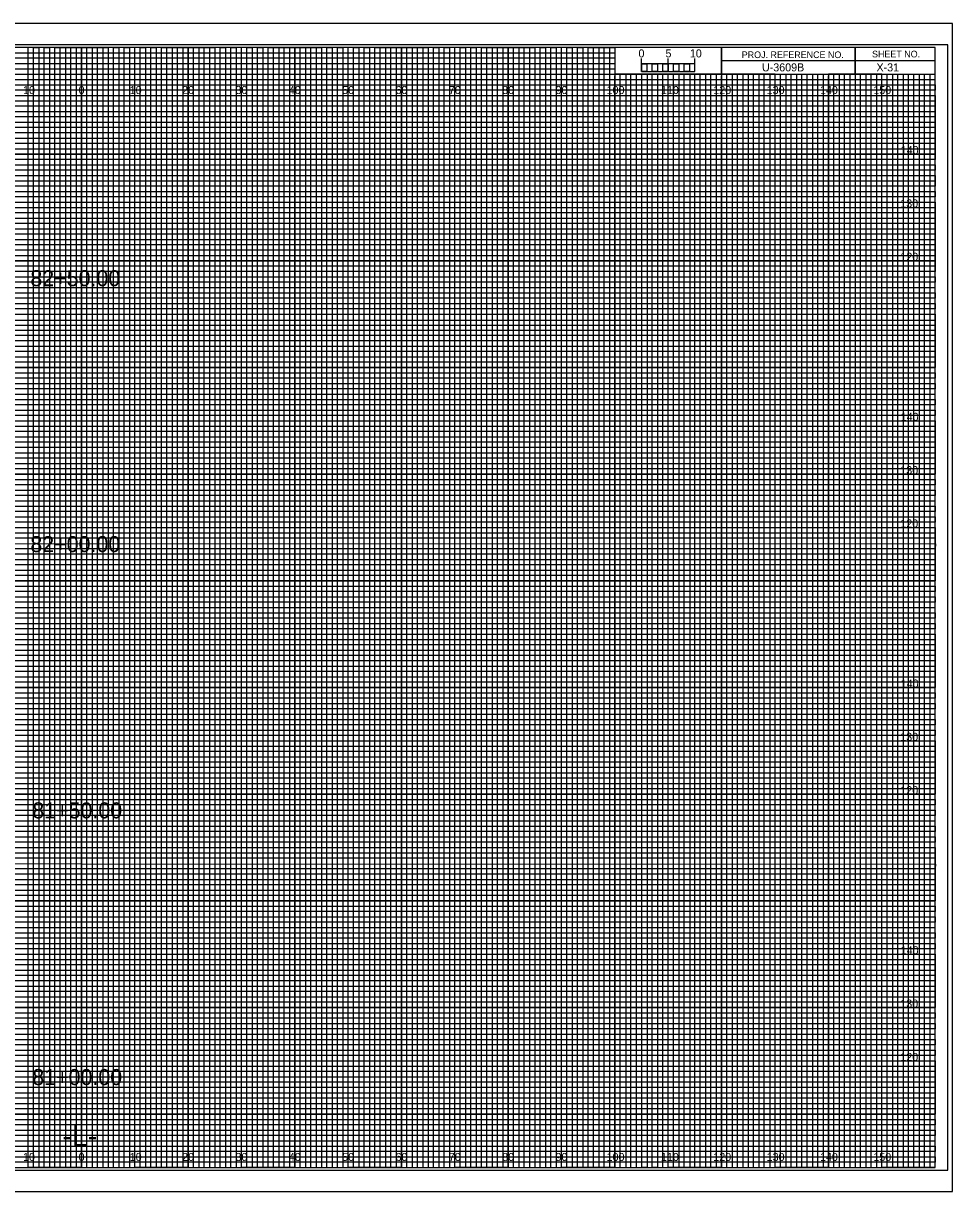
# Model space of a CAD drawing. Extents: x -13 to 329, y -17 to 10994.
# Drawn here: x 149.1 to 323.3, y 6375.5 to 6594.5 of the extents above; entities that cross this region are included whole.
import ezdxf

# ---------------------------------------------------------------- set-up
doc = ezdxf.new("R2010")
doc.units = 0
for name, color, linetype in [('Prop XS Alignment Label', 7, 'Continuous'), ('Prop XS Bar Scale Labels', 7, 'Continuous'), ('Prop XS Elevation Labels', 7, 'Continuous'), ('Prop XS Offset Labels', 7, 'Continuous'), ('Prop XS Project Number', 7, 'Continuous'), ('Prop XS Sheet Number', 7, 'Continuous'), ('Prop XS Station Labels', 7, 'Continuous'), ('Sheet Cross Section CELL', 7, 'Continuous'), ('Sheet Cross Section Grid Major CELL', 7, 'Continuous'), ('Sheet Cross Section Grid Middle CELL', 7, 'Continuous'), ('Sheet Cross Section Grid Minor 1 CELL', 7, 'Continuous'), ('Sheet Cross Section Grid Minor 2 CELL', 7, 'Continuous'), ('Sheet Cross Section Scale CELL', 7, 'Continuous'), ('Sheet Cutting Line CELL', 7, 'Continuous'), ('Sheet DOT Grid CELL', 7, 'Continuous'), ('Sheet Plot Border Inside CELL', 7, 'Continuous'), ('Sheet Plot Border Outside CELL', 7, 'Continuous')]:
    doc.layers.add(name, color=color, linetype=linetype)

msp = doc.modelspace()

# ---------------------------------------------------------------- linework, layer by layer
at = {"layer": 'Sheet Cross Section CELL'}
for p, q in [((305, 6590), (305, 6585)), ((305, 6585), (305, 6590)), ((280, 6587.5), (280, 6585)), ((320, 6587.49), (280, 6587.49)), ((280, 6585), (320, 6585))]:
    msp.add_line(p, q, dxfattribs=at)
for points in [[(320, 6590), (0, 6590), (0, 6380), (320, 6380)], [(280, 6590), (260, 6590), (260, 6585.03), (280, 6585.03)], [(320, 6590), (280, 6590), (280, 6585), (320, 6585)]]:
    msp.add_lwpolyline(points, close=True, dxfattribs=at)
at = {"layer": 'Sheet Cross Section Grid Major CELL'}
for p, q in [((150, 6590), (140, 6590)), ((150, 6380), (150, 6590)), ((170, 6590), (160, 6590)), ((160, 6590), (160, 6380)), ((170, 6380), (170, 6590)), ((190, 6590), (180, 6590)), ((180, 6590), (180, 6380)), ((190, 6380), (190, 6590)), ((210, 6590), (200, 6590)), ((200, 6590), (200, 6380)), ((210, 6380), (210, 6590)), ((230, 6590), (220, 6590)), ((220, 6590), (220, 6380)), ((230, 6380), (230, 6590)), ((250, 6590), (240, 6590)), ((240, 6590), (240, 6380)), ((250, 6380), (250, 6590)), ((260, 6590), (260, 6380)), ((270, 6380), (270, 6585)), ((290, 6585), (280, 6585)), ((280, 6585), (280, 6380)), ((290, 6380), (290, 6585)), ((310, 6585), (300, 6585)), ((300, 6585), (300, 6380)), ((310, 6380), (310, 6585)), ((160, 6380), (150, 6380)), ((180, 6380), (170, 6380)), ((200, 6380), (190, 6380)), ((220, 6380), (210, 6380)), ((240, 6380), (230, 6380)), ((260, 6380), (250, 6380)), ((280, 6380), (270, 6380)), ((300, 6380), (290, 6380)), ((320, 6380), (310, 6380)), ((320, 6380), (320, 6380))]:
    msp.add_line(p, q, dxfattribs=at)
for points in [[(0, 6580), (320, 6580), (320, 6570), (0, 6570)], [(0, 6560), (320, 6560), (320, 6550), (0, 6550)], [(0, 6540), (320, 6540), (320, 6530), (0, 6530)], [(0, 6520), (320, 6520), (320, 6510), (0, 6510)], [(0, 6500), (320, 6500), (320, 6490), (0, 6490)], [(0, 6480), (320, 6480), (320, 6470), (0, 6470)], [(0, 6460), (320, 6460), (320, 6450), (0, 6450)], [(0, 6440), (320, 6440), (320, 6430), (0, 6430)], [(0, 6420), (320, 6420), (320, 6410), (0, 6410)], [(0, 6400), (320, 6400), (320, 6390), (0, 6390)]]:
    msp.add_lwpolyline(points, dxfattribs=at)
at = {"layer": 'Sheet Cross Section Grid Middle CELL'}
for points in [[(145, 6380), (155, 6380), (155, 6590), (165, 6590), (165, 6380), (175, 6380), (175, 6590), (185, 6590), (185, 6380), (195, 6380), (195, 6590), (205, 6590), (205, 6380), (215, 6380), (215, 6590), (225, 6590), (225, 6380), (235, 6380), (235, 6590), (245, 6590), (245, 6380), (255, 6380), (255, 6590), (259.93, 6590), (260, 6590), (260, 6585), (264.99, 6585), (264.99, 6380), (275, 6380), (275, 6585), (285, 6585), (285, 6380), (295, 6380), (295, 6585), (305, 6585), (305, 6380), (315, 6380), (315, 6585)], [(0, 6585), (275, 6585)], [(0, 6565), (320, 6565), (320, 6575), (0, 6575)], [(0, 6545), (320, 6545), (320, 6555), (0, 6555)], [(0, 6525), (320, 6525), (320, 6535), (0, 6535)], [(0, 6505), (320, 6505), (320, 6515), (0, 6515)], [(0, 6485), (320, 6485), (320, 6495), (0, 6495)], [(0, 6465), (320, 6465), (320, 6475), (0, 6475)], [(0, 6445), (320, 6445), (320, 6455), (0, 6455)], [(0, 6425), (320, 6425), (320, 6435), (0, 6435)], [(0, 6405), (320, 6405), (320, 6415), (0, 6415)], [(0, 6385), (320, 6385), (320, 6395), (0, 6395)]]:
    msp.add_lwpolyline(points, dxfattribs=at)
at = {"layer": 'Sheet Cross Section Grid Minor 1 CELL'}
for p, q in [((0, 6589), (260, 6589)), ((260, 6587.98), (0, 6587.98)), ((260, 6589), (260, 6587.98)), ((0, 6587), (260, 6587)), ((260, 6585.89), (0, 6585.89)), ((260, 6587), (260, 6585.89)), ((0, 6584), (320, 6584))]:
    msp.add_line(p, q, dxfattribs=at)
for points in [[(0, 6583), (270, 6583), (320, 6583), (320, 6582), (0, 6582)], [(0, 6581), (320, 6581), (320, 6579), (0, 6579)], [(0, 6578), (320, 6578), (320, 6577), (0, 6576.98)], [(0, 6576), (320, 6576), (320, 6574), (0, 6574)], [(0, 6573), (320, 6573), (320, 6572), (0, 6572)], [(0, 6571), (320, 6571), (320, 6569), (0, 6569)], [(0, 6568), (320, 6568), (320, 6567), (0, 6567)], [(0, 6566), (320, 6566), (320, 6564), (0, 6564)], [(0, 6563), (320, 6563), (320, 6562), (0, 6562)], [(0, 6561), (320, 6561), (320, 6559), (0, 6559)], [(0, 6558), (320, 6558), (320, 6557), (0, 6557)], [(0, 6556), (320, 6556), (320, 6553.95), (320, 6553), (320, 6552), (0, 6552)], [(0, 6554), (320, 6554), (320, 6553), (0, 6553)], [(0, 6551), (320, 6551), (320, 6549), (0, 6549.03)], [(0, 6549.03), (320, 6549), (320, 6548), (0, 6548)], [(0, 6547), (320, 6547), (320, 6546), (0, 6546)], [(0, 6544), (320, 6544), (320, 6543), (0, 6543)], [(0, 6542), (320, 6542), (320, 6541), (0, 6541)], [(-0.07, 6538.89), (320, 6538.89), (320, 6537.88), (-0.07, 6537.88)], [(0, 6537), (320, 6537), (320, 6536), (0, 6536)], [(0, 6534), (320, 6534), (320, 6533), (0, 6533)], [(0, 6532), (320, 6532), (320, 6531), (0, 6531)], [(0, 6529), (320, 6529), (320, 6528), (0, 6528)], [(0, 6527), (320, 6527), (320, 6526), (0, 6526)], [(0, 6524), (320, 6524), (320, 6523), (0, 6523)], [(0, 6522), (320, 6522), (320, 6521), (0, 6521)], [(0, 6519), (320, 6519), (319.99, 6517.98), (0, 6518)], [(0, 6517), (320, 6517), (320, 6516), (0, 6516)], [(0, 6514), (320, 6514), (320, 6513), (0, 6513)], [(0, 6512), (320, 6512), (320, 6511), (0, 6511)], [(0, 6509), (320, 6509), (320, 6508), (0, 6508)], [(0, 6507), (320, 6507), (320, 6506), (0, 6506)], [(0, 6504), (320, 6504), (320, 6503), (0, 6503)], [(0, 6502), (320, 6502), (320, 6501), (0, 6501)], [(0, 6499), (320, 6499), (320, 6498), (0, 6498)], [(0, 6496.99), (320.07, 6496.91), (320, 6496), (0, 6496)], [(0, 6494), (320, 6494), (320, 6493), (0, 6493)], [(0, 6492), (320, 6492), (320, 6491), (0, 6491)], [(0, 6489), (320, 6489), (320, 6488), (0, 6488)], [(0, 6487), (320, 6487), (320, 6486), (0, 6486)], [(0, 6484), (320, 6484), (320, 6483), (0, 6483)], [(0, 6482), (320, 6482), (320, 6481), (0, 6481)], [(0, 6479), (320, 6479), (320, 6478), (0, 6478)], [(0, 6477), (320, 6477), (320, 6476), (0, 6476)], [(0, 6474), (320, 6474), (320, 6473), (0, 6473)], [(0, 6472), (320, 6472), (320, 6471), (0, 6471)], [(0, 6469), (320, 6469), (320, 6468), (0, 6468)], [(0, 6467), (320, 6467), (320, 6466), (0, 6466)], [(0, 6464), (320, 6464), (320, 6463), (0, 6463)], [(0, 6462), (320, 6462), (320, 6461), (0, 6461)], [(0, 6459), (320, 6459), (319.99, 6457.98), (0, 6458)], [(0, 6457), (320, 6457), (320, 6456), (0, 6456)], [(0, 6454), (320, 6454), (320, 6453), (0, 6453)], [(0, 6452), (320, 6452), (320, 6451), (0, 6451)], [(0, 6449), (320, 6449), (320, 6448), (0, 6448)], [(0, 6447), (320, 6447), (320, 6446), (0, 6446)], [(0, 6444), (320, 6444), (320, 6443), (0, 6443)], [(0, 6442), (320, 6442), (320, 6441), (0, 6441)], [(0, 6439), (320, 6439), (320, 6438), (0, 6438)], [(0, 6436.99), (320.07, 6436.91), (320, 6436), (0, 6436)], [(0, 6434), (320, 6434), (320, 6433), (0, 6433)], [(0, 6432), (320, 6432), (320, 6431), (0, 6431)], [(0, 6429), (320, 6429), (320, 6428), (0, 6428)], [(0, 6427), (320, 6427), (320, 6426), (0, 6426)], [(0, 6424), (320, 6424), (320, 6423), (0, 6423)], [(0, 6422), (320, 6422), (320, 6421), (0, 6421)], [(0, 6419), (320, 6419), (320, 6418), (0, 6418)], [(0, 6417), (320, 6417), (320, 6416), (0, 6416)], [(0, 6414), (320, 6414), (320, 6413), (0, 6413)], [(0, 6412), (320, 6412), (320, 6411), (0, 6411)], [(0, 6409), (320, 6409), (320, 6408), (0, 6408)], [(0, 6407), (320, 6407), (320, 6406), (0, 6406)], [(0, 6404), (320, 6404), (320, 6403), (0, 6403)], [(0, 6402), (320, 6402), (320, 6401), (0, 6401)], [(0, 6399), (320, 6399), (320, 6398), (0, 6398)], [(0, 6397), (320, 6397), (320, 6396), (0, 6396)], [(0, 6394), (320, 6394), (320, 6393), (0, 6393)], [(0, 6392), (320, 6392), (320, 6391), (0, 6391)], [(0, 6389), (320, 6389), (320, 6388), (0, 6388)], [(0, 6387), (320, 6387), (320, 6386), (0, 6386)], [(0, 6384), (320, 6384), (320, 6383), (0, 6383)], [(0, 6382), (320, 6382), (320, 6381), (0, 6381)]]:
    msp.add_lwpolyline(points, dxfattribs=at)
at = {"layer": 'Sheet Cross Section Grid Minor 2 CELL'}
for p, q in [((267, 6585), (266.01, 6585)), ((266.01, 6585), (266.01, 6380)), ((267, 6380), (267, 6585)), ((269, 6585), (268, 6585)), ((268, 6585), (268, 6380)), ((269, 6380), (269, 6585)), ((266.01, 6380), (265, 6380)), ((268, 6380), (267, 6380))]:
    msp.add_line(p, q, dxfattribs=at)
for points in [[(150, 6380), (151, 6380), (151, 6590), (152, 6590), (152, 6380)], [(152, 6380), (153, 6380), (153, 6590), (154, 6590), (154, 6380)], [(155, 6380), (156, 6380), (156, 6590), (157, 6590), (157, 6380)], [(157, 6380), (158, 6380), (158, 6590), (159, 6590), (159, 6380)], [(160, 6380), (161, 6380), (161, 6590), (162, 6590), (162, 6380)], [(162, 6380), (163, 6380), (163, 6590), (164, 6590), (164, 6380)], [(165, 6380), (166, 6380), (166, 6590), (167, 6590), (167, 6380)], [(167, 6380), (168, 6380), (168, 6590), (169, 6590), (169, 6380)], [(170, 6380), (171, 6380), (171, 6590), (172, 6590), (172, 6380)], [(172, 6380), (173, 6380), (173, 6590), (174, 6590), (174, 6380)], [(175, 6380), (176, 6380), (176, 6590), (177, 6590), (177, 6380)], [(177, 6380), (178, 6380), (178, 6590), (179, 6590), (179, 6380)], [(180, 6380), (181, 6380), (181, 6590), (182, 6590), (182, 6380)], [(182, 6380), (183, 6380), (183, 6590), (184, 6590), (184, 6380)], [(185, 6380), (186, 6380), (186, 6590), (187, 6590), (187, 6380)], [(187, 6380), (188, 6380), (188, 6590), (189, 6590), (189, 6380)], [(190, 6380), (191, 6380), (191, 6590), (192, 6590), (192, 6380)], [(192, 6380), (193, 6380), (193, 6590), (194, 6590), (194, 6380)], [(195, 6380), (196, 6380), (196, 6590), (197, 6590), (197, 6380)], [(197, 6380), (198, 6380), (198, 6590), (199, 6590), (199, 6380)], [(200, 6380), (201, 6380), (201, 6590), (202, 6590), (202, 6380)], [(202, 6380), (203, 6380), (203, 6590), (204, 6590), (204, 6380)], [(205, 6380), (206, 6380), (206, 6590), (207, 6590), (207, 6380)], [(207, 6380), (208, 6380), (208, 6590), (209, 6590), (209, 6380)], [(210, 6380), (211, 6380), (211, 6590), (212, 6590), (212, 6380)], [(212, 6380), (213, 6380), (213, 6590), (214, 6590), (214, 6380)], [(215, 6380), (216, 6380), (216, 6590), (217, 6590), (217, 6380)], [(217, 6380), (218, 6380), (218, 6590), (219, 6590), (219, 6380)], [(220, 6380), (221, 6380), (221, 6590), (222, 6590), (222, 6380)], [(222, 6380), (223, 6380), (223, 6590), (224, 6590), (224, 6380)], [(225, 6380), (226, 6380), (226, 6590), (227, 6590), (227, 6380)], [(227, 6380), (228, 6380), (228, 6590), (229, 6590), (229, 6380)], [(230, 6380), (231, 6380), (231, 6590), (232, 6590), (232, 6380)], [(232, 6380), (233, 6380), (233, 6590), (234, 6590), (234, 6380)], [(235, 6380), (236, 6380), (236, 6590), (237, 6590), (237, 6380)], [(237, 6380), (238, 6380), (238, 6590), (239, 6590), (239, 6380)], [(240, 6380), (241, 6380), (241, 6590), (242, 6590), (242, 6380)], [(242, 6380), (243, 6380), (243, 6590), (244, 6590), (244, 6380)], [(245, 6380), (246, 6380), (246, 6590), (247, 6590), (247, 6380)], [(247, 6380), (248, 6380), (248, 6590), (249, 6590), (249, 6380)], [(250, 6380), (251, 6380), (251, 6590), (252, 6590), (252, 6380)], [(252, 6380), (253, 6380), (253, 6590), (254, 6590), (254, 6380)], [(255, 6380), (256, 6380), (256, 6590), (257, 6590), (257, 6380)], [(257, 6380), (258, 6380), (258, 6590), (259, 6590), (259, 6380)], [(260, 6380), (261, 6380), (261, 6585), (262.02, 6585), (262.02, 6380)], [(262, 6380), (263, 6380), (263, 6585), (263.99, 6585), (263.99, 6380)], [(270, 6380), (270.98, 6380), (270.98, 6585), (272, 6585), (272, 6380)], [(272, 6380), (273, 6380), (273, 6585), (274.05, 6585), (274.05, 6380)], [(275, 6380), (276, 6380), (276, 6585), (277, 6585), (277, 6380)], [(277, 6380), (278, 6380), (278, 6585), (279, 6585), (279, 6380)], [(280, 6380), (281, 6380), (281, 6585), (282, 6585), (282, 6380)], [(282, 6380), (283, 6380), (283, 6585), (284, 6585), (284, 6380)], [(285, 6380), (286, 6380), (286, 6585), (287, 6585), (287, 6380)], [(287, 6380), (288, 6380), (288, 6585), (289, 6585), (289, 6380)], [(290, 6380), (291, 6380), (291, 6585), (292, 6585), (292, 6380)], [(292, 6380), (293, 6380), (293, 6585), (294, 6585), (294, 6380)], [(295, 6380), (296, 6380), (296, 6585), (297, 6585), (297, 6380)], [(297, 6380), (298, 6380), (298, 6585), (299, 6585), (299, 6380)], [(300, 6380), (301, 6380), (301, 6585), (302, 6585), (302, 6380)], [(302, 6380), (303, 6380), (303, 6585), (304, 6585), (304, 6380)], [(305, 6380), (306, 6380), (306, 6585), (307, 6585), (307, 6380)], [(307, 6380), (308, 6380), (308, 6585), (309, 6585), (309, 6380)], [(310, 6380), (311, 6380), (311, 6585), (312, 6585), (312, 6380)], [(312, 6380), (313, 6380), (313, 6585), (314, 6585), (314, 6380)], [(315, 6380), (316, 6380), (316, 6585), (317, 6585), (317, 6380)], [(317, 6380), (318, 6380), (318, 6585), (319, 6585), (319, 6380)]]:
    msp.add_lwpolyline(points, dxfattribs=at)
at = {"layer": 'Sheet Cross Section Scale CELL'}
for p, q in [((265, 6585.49), (265, 6587.9)), ((265, 6586.9), (265, 6587.9)), ((270, 6585.49), (270, 6587.9)), ((275, 6585.49), (275, 6587.9)), ((275, 6586.9), (275, 6587.9))]:
    msp.add_line(p, q, dxfattribs=at)
for points in [[(275, 6586.9), (265, 6586.9), (265, 6585.49), (275, 6585.49)], [(265, 6586.9), (266, 6586.9), (266, 6585.49), (265, 6585.49)], [(267, 6586.9), (268, 6586.9), (268, 6585.49), (267, 6585.49)], [(269, 6586.9), (270, 6586.9), (270, 6585.49), (269, 6585.49)], [(271, 6586.9), (272, 6586.9), (272, 6585.49), (271, 6585.49)], [(273, 6586.9), (274, 6586.9), (274, 6585.49), (273, 6585.49)]]:
    msp.add_lwpolyline(points, close=True, dxfattribs=at)
at = {"layer": 'Sheet Cutting Line CELL'}
for p, q in [((323.3, 6594.5), (-13.4, 6594.5)), ((-13.4, 6375.5), (323.3, 6375.5))]:
    msp.add_line(p, q, dxfattribs=at)
at = {"layer": 'Sheet DOT Grid CELL'}
for p, q in [((150, 6380), (150, 6590)), ((160, 6380), (160, 6590)), ((170, 6380), (170, 6590)), ((180, 6380), (180, 6590)), ((190, 6380), (190, 6590)), ((200, 6380), (200, 6590)), ((210, 6380), (210, 6590)), ((220, 6380), (220, 6590)), ((230, 6380), (230, 6590)), ((240, 6380), (240, 6590)), ((250, 6380), (250, 6590)), ((260, 6380), (260, 6584.69)), ((270, 6380), (270, 6584.69)), ((280, 6380), (280, 6584.69)), ((290, 6380), (290, 6584.69)), ((300, 6380), (300, 6584.69)), ((310, 6380), (310, 6584.69)), ((0, 6580), (320, 6580)), ((0, 6570), (320, 6570)), ((0, 6560), (320, 6560)), ((0, 6550), (320, 6550)), ((0, 6540), (320, 6540)), ((0, 6530), (320, 6530)), ((0, 6520), (320, 6520)), ((0, 6510), (320, 6510)), ((0, 6500), (320, 6500)), ((0, 6490), (320, 6490)), ((0, 6480), (320, 6480)), ((0, 6470), (320, 6470)), ((0, 6460), (320, 6460)), ((0, 6450), (320, 6450)), ((0, 6440), (320, 6440)), ((0, 6430), (320, 6430)), ((0, 6420), (320, 6420)), ((0, 6410), (320, 6410)), ((0, 6400), (320, 6400)), ((0, 6390), (320, 6390))]:
    msp.add_line(p, q, dxfattribs=at)
at = {"layer": 'Sheet Plot Border Inside CELL'}
msp.add_lwpolyline([(-10.8, 6379.5), (322.4, 6379.5), (322.4, 6590.5), (-10.8, 6590.5)], close=True, dxfattribs=at)
at = {"layer": 'Sheet Plot Border Outside CELL'}
msp.add_lwpolyline([(-13.4, 6375.5), (323.3, 6375.5), (323.3, 6594.5), (-13.4, 6594.5)], close=True, dxfattribs=at)

# ---------------------------------------------------------------- texts
at = {"layer": 'Prop XS Alignment Label'}
msp.add_text('-L-', height=4, dxfattribs=at).set_placement((156.42, 6384))
at = {"layer": 'Prop XS Bar Scale Labels'}
for s, p in [('5', (269.47, 6588.12)), ('10', (274.04, 6588.12))]:
    msp.add_text(s, height=1.5, dxfattribs=at).set_placement(p)
at = {"layer": 'Prop XS Elevation Labels'}
for s, p in [('140', (313.57, 6570)), ('130', (313.49, 6560)), ('120', (313.5, 6550)), ('140', (313.57, 6520)), ('130', (313.49, 6510)), ('120', (313.5, 6500)), ('140', (313.57, 6470)), ('130', (313.49, 6460)), ('120', (313.5, 6450)), ('140', (313.57, 6420)), ('130', (313.49, 6410)), ('120', (313.5, 6400))]:
    msp.add_text(s, height=1.5, dxfattribs=at).set_placement(p)
at = {"layer": 'Prop XS Offset Labels'}
for s, p in [('10', (149.04, 6581.25)), ('0', (159.45, 6581.25)), ('0', (159.45, 6581.25)), ('10', (169.04, 6581.25)), ('20', (178.86, 6581.25)), ('30', (188.86, 6581.25)), ('40', (198.86, 6581.25)), ('50', (208.86, 6581.25)), ('60', (218.86, 6581.25)), ('70', (228.86, 6581.25)), ('80', (238.86, 6581.25)), ('90', (248.86, 6581.25)), ('100', (258.44, 6581.25)), ('110', (268.62, 6581.25)), ('120', (278.44, 6581.25)), ('130', (288.44, 6581.25)), ('140', (298.44, 6581.25)), ('150', (308.44, 6581.25)), ('10', (149.04, 6381.25)), ('0', (159.45, 6381.25)), ('0', (159.45, 6381.25)), ('10', (169.04, 6381.25)), ('20', (178.86, 6381.25)), ('30', (188.86, 6381.25)), ('40', (198.86, 6381.25)), ('50', (208.86, 6381.25)), ('60', (218.86, 6381.25)), ('70', (228.86, 6381.25)), ('80', (238.86, 6381.25)), ('90', (248.86, 6381.25)), ('100', (258.44, 6381.25)), ('110', (268.62, 6381.25)), ('120', (278.44, 6381.25)), ('130', (288.44, 6381.25)), ('140', (298.44, 6381.25)), ('150', (308.44, 6381.25))]:
    msp.add_text(s, height=1.5, dxfattribs=at).set_placement(p)
at = {"layer": 'Prop XS Project Number'}
msp.add_text('U-3609B', height=1.5, dxfattribs=at).set_placement((287.56, 6585.5))
at = {"layer": 'Prop XS Sheet Number'}
msp.add_text('X-31', height=1.5, dxfattribs=at).set_placement((309.02, 6585.5))
at = {"layer": 'Prop XS Station Labels'}
for s, p in [('82+50.00', (150.41, 6545.23)), ('82+00.00', (150.41, 6495.39)), ('81+50.00', (150.77, 6445.47)), ('81+00.00', (150.77, 6395.48))]:
    msp.add_text(s, height=3, dxfattribs=at).set_placement(p)
at = {"layer": 'Sheet Cross Section CELL'}
for s, p in [('PROJ. REFERENCE NO.', (283.77, 6587.99)), ('SHEET NO.', (308.19, 6588.12))]:
    msp.add_text(s, height=1.25, dxfattribs=at).set_placement(p)
at = {"layer": 'Sheet Cross Section Scale CELL'}
msp.add_text('0', height=1.5, dxfattribs=at).set_placement((264.41, 6588.12))

doc.saveas('drawing.dxf')
